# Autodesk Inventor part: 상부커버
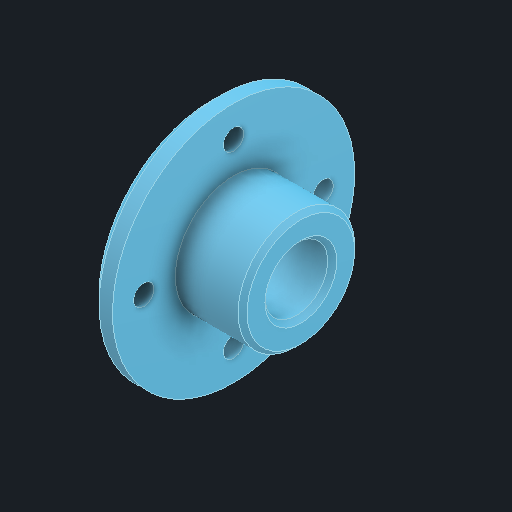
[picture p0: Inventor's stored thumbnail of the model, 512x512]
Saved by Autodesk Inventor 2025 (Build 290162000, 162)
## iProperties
Created: 2025-08
Part Number: 상부커버
Material: 알루미늄 6061
Document SubType Name: Modeling
Designer: infra10
Density: 2.71 g/cm^3
Appearance: 기본값
Author: jhkim
Sending System: Autodesk Inventor 2026
Preprocessor: ST-DEVELOPER v20.1
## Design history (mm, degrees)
feature "솔리드1"
node "솔리드2"
